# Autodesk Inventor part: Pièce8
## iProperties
Shininess: 64.0
Length Units: 11269
Angle Units: 11279
Time Units: 11290
Mass Units: 11283
Length Display Precision: 3
Angle Display Precision: 2
Compacted: True
Part Number: Pièce8
Document SubType Name: Modeling
Created: 2004-06
Material: Par défaut
Designer: administrateur
Density: 0.0
Volumn: 0.0
Area: 0.0
PropertySet Name: Model Information
Control State: 0
Master: False
Checked Out: False
Author: administrateur
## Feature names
1. Extrusion1
2. Extrusion2
3. Extrusion3
4. Balayage1
5. Réseau rectangulaire1 [Rectangular Pattern]
